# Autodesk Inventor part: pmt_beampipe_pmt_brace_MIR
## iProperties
Shininess: 64.0
Length Units: 11272
Angle Units: 11279
Time Units: 11290
Mass Units: 11286
Length Display Precision: 3
Angle Display Precision: 2
Compacted: True
Part Number: pmt_beampipe_pmt_brace_MIR
Document SubType Name: Modeling
Created: 2004-08
Designer: John Blackburn
Material: Aluminum-6061
Manufacturer: Standard
Standards Organization: Custom
Density: 0.0
Volumn: 0.0
Area: 0.0
PropertySet Name: Model Information
Control State: 0
Master: False
Checked Out: False
Author: John Blackburn
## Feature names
1. Derived Body1 [Tagging]
